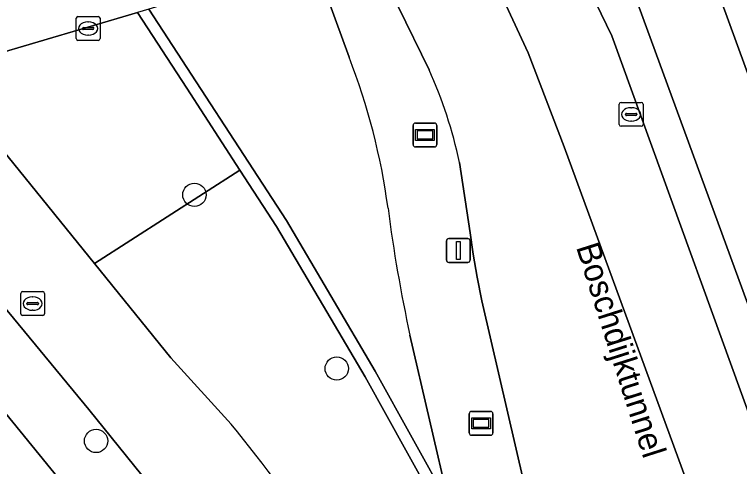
# Model space of a CAD drawing. Extents: x 160806 to 161707, y 383696 to 384148.
# Drawn here: x 161055.47 to 161085.88, y 383764.83 to 383783.78 of the extents above; entities that cross this region are included whole.
import ezdxf

# ---------------------------------------------------------------- set-up
doc = ezdxf.new("R2010")
doc.units = 0
for name, color, linetype in [('IMGEO_Berm_groen', 7, 'Continuous'), ('IMGEO_Berm_halfverhard', 7, 'Continuous'), ('IMGEO_Boom', 7, 'Continuous'), ('IMGEO_Brandkraan', 7, 'Continuous'), ('IMGEO_Fietspad_open', 7, 'Continuous'), ('IMGEO_Groenvoorziening', 7, 'Continuous'), ('IMGEO_Kolk', 7, 'Continuous'), ('IMGEO_Lichtmast', 7, 'Continuous'), ('IMGEO_Muur', 7, 'Continuous'), ('IMGEO_Openbare_ruimte_label', 7, 'Continuous'), ('IMGEO_OVBaan_gesloten', 7, 'Continuous'), ('IMGEO_Reclamebord', 7, 'Continuous'), ('IMGEO_Rijbaan_lokaal_gesloten', 7, 'Continuous'), ('IMGEO_Rioolput', 7, 'Continuous'), ('IMGEO_Voetpad_open', 7, 'Continuous'), ('IMGEO_Wegwijzer', 7, 'Continuous')]:
    doc.layers.add(name, color=color, linetype=linetype)

msp = doc.modelspace()

# ---------------------------------------------------------------- linework, layer by layer
at = {"layer": 'IMGEO_Berm_groen'}
msp.add_lwpolyline([(161069.508, 383781.989), (161068.01, 383786.104), (161061.104, 383784.003), (161066.874, 383775.139), (161070.603, 383768.827), (161073.707, 383763.229), (161072.059, 383770.328)], dxfattribs=at)
for centre, radius, start, end in [((161043.761, 383771.984), 27.622, 7.645, 21.2353), ((161134.494, 383783.86), 63.885, 187.37512, 192.22857)]:
    msp.add_arc(centre, radius, start, end, dxfattribs=at)
at = {"layer": 'IMGEO_Berm_halfverhard'}
msp.add_lwpolyline([(161086.058, 383784.64), (161083.782, 383790.902), (161082.829, 383790.612), (161096.146, 383754.129), (161097.094, 383754.459)], close=True, dxfattribs=at)
for points in [[(161080.062, 383788.476), (161079.546, 383789.613), (161078.224, 383789.211), (161077.524, 383788.998), (161078.277, 383787.537), (161080.521, 383782.879), (161094.759, 383743.637)], [(161095.134, 383747.328), (161080.062, 383788.476)]]:
    msp.add_lwpolyline(points, dxfattribs=at)
at = {"layer": 'IMGEO_Boom'}
for centre in [(161063.016, 383776.218), (161068.987, 383768.934), (161058.891, 383765.899)]:
    msp.add_circle(centre, 0.489, dxfattribs=at)
at = {"layer": 'IMGEO_Brandkraan'}
for p, q in [((161055.804, 383772.159), (161056.656, 383772.159)), ((161055.729, 383771.233), (161055.729, 383772.085)), ((161056.217, 383771.939), (161056.242, 383771.939)), ((161056.73, 383772.085), (161056.73, 383771.233)), ((161055.988, 383771.653), (161055.988, 383771.665)), ((161056.426, 383771.616), (161056.028, 383771.616)), ((161056.031, 383771.702), (161056.429, 383771.702)), ((161056.472, 383771.665), (161056.472, 383771.653)), ((161056.24, 383771.379), (161056.215, 383771.379)), ((161056.656, 383771.159), (161055.804, 383771.159))]:
    msp.add_line(p, q, dxfattribs=at)
for points in [[(161055.804, 383772.159), (161056.656, 383772.159)], [(161055.729, 383771.233), (161055.729, 383772.085)], [(161056.73, 383772.085), (161056.73, 383771.233)], [(161056.656, 383771.159), (161055.804, 383771.159)]]:
    msp.add_lwpolyline(points, dxfattribs=at)
for centre, radius, start, end in [((161055.806, 383772.083), 0.0765, 91.552, 178.448), ((161055.806, 383772.083), 0.0765, 91.552, 178.448), ((161056.654, 383772.083), 0.0765, 1.552, 88.448), ((161056.654, 383772.083), 0.0765, 1.552, 88.448), ((161056.028, 383771.662), 0.0403, 85.8775, 175.7526), ((161056.025, 383771.652), 0.0366, 178.938, 274.7102), ((161056.429, 383771.659), 0.043, 264.8664, 352.4533), ((161056.433, 383771.664), 0.0386, 1.7309, 96.639), ((161055.806, 383771.235), 0.0765, 181.552, 268.448), ((161055.806, 383771.235), 0.0765, 181.552, 268.448), ((161056.654, 383771.235), 0.0765, 271.552, 358.448), ((161056.654, 383771.235), 0.0765, 271.552, 358.448)]:
    msp.add_arc(centre, radius, start, end, dxfattribs=at)
for centre, major_axis, ratio, start_param, end_param in [((161056.216, 383771.659), (-0.387, 0.002), 0.722429, 4.712389, 7.853982), ((161056.241, 383771.659), (-0.39, 0.002), 0.717154, 1.570796, 4.712389)]:
    msp.add_ellipse(centre, major_axis=major_axis, ratio=ratio, start_param=start_param, end_param=end_param, dxfattribs=at)
at = {"layer": 'IMGEO_Fietspad_open'}
for points in [[(161064.553, 383766.608), (161062.033, 383769.384), (161058.823, 383773.343), (161052.286, 383781.408), (161048.16, 383779.877)], [(161048.827, 383779.023), (161058.581, 383767.212), (161063.615, 383760.981)]]:
    msp.add_lwpolyline(points, dxfattribs=at)
msp.add_arc((160988.276, 383704.668), 98.259, 35.17137, 39.0782, dxfattribs=at)
at = {"layer": 'IMGEO_Groenvoorziening'}
msp.add_lwpolyline([(161062.692, 383780.695), (161060.635, 383783.865), (161052.286, 383781.408), (161058.823, 383773.343), (161064.925, 383777.254)], close=True, dxfattribs=at)
for points in [[(161066.462, 383774.885), (161064.925, 383777.254), (161058.823, 383773.343), (161062.033, 383769.384), (161064.553, 383766.608)], [(161053.727, 383764.339), (161055.888, 383755.75), (161062.76, 383757.656), (161048.332, 383775.339)], [(161071.934, 383755.585), (161072.088, 383755.217), (161073.898, 383750.874), (161074.242, 383750), (161077.712, 383741.17), (161080.57, 383734.119), (161080.705, 383733.661), (161084.716, 383740.669), (161084.276, 383740.472), (161079.903, 383750), (161075.811, 383758.082), (161073.73, 383762.192), (161070.184, 383768.589), (161066.462, 383774.885)]]:
    msp.add_lwpolyline(points, dxfattribs=at)
msp.add_arc((160988.276, 383704.668), 98.259, 35.17137, 39.0782, dxfattribs=at)
at = {"layer": 'IMGEO_Kolk'}
for p, q in [((161058.056, 383782.768), (161058.056, 383783.62)), ((161058.131, 383783.694), (161058.983, 383783.694)), ((161058.544, 383783.474), (161058.569, 383783.474)), ((161059.057, 383783.62), (161059.057, 383782.768)), ((161058.315, 383783.188), (161058.315, 383783.2)), ((161058.753, 383783.151), (161058.355, 383783.151)), ((161058.358, 383783.237), (161058.756, 383783.237)), ((161058.799, 383783.2), (161058.799, 383783.188)), ((161058.567, 383782.914), (161058.542, 383782.914)), ((161058.983, 383782.694), (161058.131, 383782.694))]:
    msp.add_line(p, q, dxfattribs=at)
for points in [[(161058.056, 383782.768), (161058.056, 383783.62)], [(161058.131, 383783.694), (161058.983, 383783.694)], [(161059.057, 383783.62), (161059.057, 383782.768)], [(161058.983, 383782.694), (161058.131, 383782.694)]]:
    msp.add_lwpolyline(points, dxfattribs=at)
for centre, radius, start, end in [((161058.133, 383783.618), 0.0765, 91.552, 178.448), ((161058.133, 383783.618), 0.0765, 91.552, 178.448), ((161058.981, 383783.618), 0.0765, 1.552, 88.448), ((161058.981, 383783.618), 0.0765, 1.552, 88.448), ((161058.355, 383783.197), 0.0403, 85.8775, 175.7526), ((161058.352, 383783.187), 0.0366, 178.938, 274.7102), ((161058.756, 383783.194), 0.043, 264.8664, 352.4533), ((161058.76, 383783.199), 0.0386, 1.7309, 96.639), ((161058.133, 383782.77), 0.0765, 181.552, 268.448), ((161058.133, 383782.77), 0.0765, 181.552, 268.448), ((161058.981, 383782.77), 0.0765, 271.552, 358.448), ((161058.981, 383782.77), 0.0765, 271.552, 358.448)]:
    msp.add_arc(centre, radius, start, end, dxfattribs=at)
for centre, major_axis, ratio, start_param, end_param in [((161058.543, 383783.194), (-0.387, 0.002), 0.722429, 4.712389, 7.853982), ((161058.568, 383783.194), (-0.39, 0.002), 0.717154, 1.570796, 4.712389)]:
    msp.add_ellipse(centre, major_axis=major_axis, ratio=ratio, start_param=start_param, end_param=end_param, dxfattribs=at)
at = {"layer": 'IMGEO_Lichtmast'}
for p, q in [((161073.689, 383774.384), (161074.479, 383774.384)), ((161074.479, 383774.384), (161073.689, 383774.384)), ((161073.589, 383773.484), (161073.589, 383774.284)), ((161073.589, 383774.284), (161073.589, 383773.484)), ((161074.579, 383774.284), (161074.579, 383773.484)), ((161074.579, 383773.484), (161074.579, 383774.284)), ((161074.479, 383773.384), (161073.689, 383773.384)), ((161073.689, 383773.384), (161074.479, 383773.384))]:
    msp.add_line(p, q, dxfattribs=at)
msp.add_lwpolyline([(161074.009, 383774.259), (161074.159, 383774.259), (161074.159, 383773.509), (161074.009, 383773.509), (161074.009, 383774.259)], dxfattribs=at)
for centre, start, end in [((161073.689, 383774.284), 90, 180), ((161073.689, 383774.284), 90, 180), ((161074.479, 383774.284), 0, 90), ((161074.479, 383774.284), 360, 90), ((161073.689, 383773.484), 180, 270), ((161073.689, 383773.484), 180, 270), ((161074.479, 383773.484), 270, 0), ((161074.479, 383773.484), 270, 0)]:
    msp.add_arc(centre, 0.1, start, end, dxfattribs=at)
at = {"layer": 'IMGEO_Muur'}
msp.add_lwpolyline([(161073.707, 383763.229), (161070.603, 383768.827), (161066.874, 383775.139), (161061.104, 383784.003), (161060.635, 383783.865), (161062.692, 383780.695), (161064.925, 383777.254), (161066.462, 383774.885), (161070.184, 383768.589), (161073.73, 383762.192), (161075.811, 383758.082), (161079.903, 383750), (161084.276, 383740.472), (161084.716, 383740.669), (161080.436, 383750)], close=True, dxfattribs=at)
at = {"layer": 'IMGEO_OVBaan_gesloten'}
msp.add_lwpolyline([(161098.248, 383750), (161097.827, 383750), (161097.566, 383750.295), (161097.284, 383751.013), (161096.146, 383754.129), (161082.829, 383790.612), (161079.643, 383789.643), (161080.062, 383788.476), (161095.134, 383747.328)], dxfattribs=at)
at = {"layer": 'IMGEO_Reclamebord'}
for p, q in [((161074.546, 383766.238), (161074.546, 383767.038)), ((161074.546, 383767.038), (161074.546, 383766.238)), ((161074.646, 383767.138), (161075.436, 383767.138)), ((161075.436, 383767.138), (161074.646, 383767.138)), ((161075.536, 383767.038), (161075.536, 383766.238)), ((161075.536, 383766.238), (161075.536, 383767.038)), ((161075.436, 383766.138), (161074.646, 383766.138)), ((161074.646, 383766.138), (161075.436, 383766.138))]:
    msp.add_line(p, q, dxfattribs=at)
for points in [[(161074.647, 383766.87), (161075.435, 383766.87), (161075.435, 383766.406), (161074.647, 383766.406), (161074.647, 383766.87)], [(161074.712, 383766.805), (161074.712, 383766.471), (161075.37, 383766.471), (161075.37, 383766.805), (161074.712, 383766.805)]]:
    msp.add_lwpolyline(points, dxfattribs=at)
for centre, start, end in [((161074.646, 383767.038), 90, 180), ((161074.646, 383767.038), 90, 180), ((161075.436, 383767.038), 0, 90), ((161075.436, 383767.038), 360, 90), ((161074.646, 383766.238), 180, 270), ((161074.646, 383766.238), 180, 270), ((161075.436, 383766.238), 270, 0), ((161075.436, 383766.238), 270, 0)]:
    msp.add_arc(centre, 0.1, start, end, dxfattribs=at)
at = {"layer": 'IMGEO_Rijbaan_lokaal_gesloten'}
for points in [[(161080.521, 383782.879), (161078.277, 383787.537), (161077.524, 383788.998), (161075.001, 383788.231), (161074.06, 383787.945), (161075.725, 383784.96), (161077.022, 383782.168), (161078.529, 383778.234), (161084.322, 383762.444), (161094.418, 383735.279), (161098.056, 383725.946), (161105.565, 383706.821), (161108.924, 383707.18), (161108.812, 383707.52), (161103.024, 383722.158)], [(161074.06, 383787.945), (161071.12, 383787.05), (161070.257, 383786.787), (161072.86, 383781.463)], [(161097.209, 383718.989), (161102.075, 383706.764), (161102.196, 383706.461), (161105.565, 383706.821), (161098.056, 383725.946), (161094.418, 383735.279), (161084.322, 383762.444), (161078.529, 383778.234), (161077.022, 383782.168), (161075.725, 383784.96), (161074.06, 383787.945)], [(161094.759, 383743.637), (161080.521, 383782.879)], [(161074.138, 383777.58), (161074.579, 383774.627), (161074.704, 383773.732), (161074.871, 383772.76), (161075.07, 383771.78), (161077.219, 383762.531)]]:
    msp.add_lwpolyline(points, dxfattribs=at)
msp.add_arc((161054.965, 383773.421), 19.619, 12.2378, 24.1977, dxfattribs=at)
at = {"layer": 'IMGEO_Rioolput'}
for p, q in [((161080.912, 383780.092), (161081.764, 383780.092)), ((161080.837, 383779.166), (161080.837, 383780.018)), ((161081.325, 383779.872), (161081.35, 383779.872)), ((161081.838, 383780.018), (161081.838, 383779.166)), ((161081.096, 383779.586), (161081.096, 383779.598)), ((161081.534, 383779.549), (161081.136, 383779.549)), ((161081.139, 383779.635), (161081.537, 383779.635)), ((161081.58, 383779.598), (161081.58, 383779.586)), ((161081.348, 383779.312), (161081.323, 383779.312)), ((161081.764, 383779.092), (161080.912, 383779.092))]:
    msp.add_line(p, q, dxfattribs=at)
for points in [[(161080.912, 383780.092), (161081.764, 383780.092)], [(161080.837, 383779.166), (161080.837, 383780.018)], [(161081.838, 383780.018), (161081.838, 383779.166)], [(161081.764, 383779.092), (161080.912, 383779.092)]]:
    msp.add_lwpolyline(points, dxfattribs=at)
for centre, radius, start, end in [((161080.914, 383780.016), 0.0765, 91.552, 178.448), ((161080.914, 383780.016), 0.0765, 91.552, 178.448), ((161081.762, 383780.016), 0.0765, 1.552, 88.448), ((161081.762, 383780.016), 0.0765, 1.552, 88.448), ((161081.136, 383779.595), 0.0403, 85.8775, 175.7526), ((161081.133, 383779.585), 0.0366, 178.938, 274.7102), ((161081.537, 383779.592), 0.043, 264.8664, 352.4533), ((161081.541, 383779.597), 0.0386, 1.7309, 96.639), ((161080.914, 383779.168), 0.0765, 181.552, 268.448), ((161080.914, 383779.168), 0.0765, 181.552, 268.448), ((161081.762, 383779.168), 0.0765, 271.552, 358.448), ((161081.762, 383779.168), 0.0765, 271.552, 358.448)]:
    msp.add_arc(centre, radius, start, end, dxfattribs=at)
for centre, major_axis, ratio, start_param, end_param in [((161081.324, 383779.592), (-0.387, 0.002), 0.722429, 4.712389, 7.853982), ((161081.349, 383779.592), (-0.39, 0.002), 0.717154, 1.570796, 4.712389)]:
    msp.add_ellipse(centre, major_axis=major_axis, ratio=ratio, start_param=start_param, end_param=end_param, dxfattribs=at)
at = {"layer": 'IMGEO_Voetpad_open'}
for points in [[(161072.86, 383781.463), (161070.257, 383786.787), (161068.01, 383786.104), (161069.508, 383781.989)], [(161051.286, 383782.642), (161052.286, 383781.408), (161060.635, 383783.865)], [(161063.615, 383760.981), (161058.581, 383767.212), (161048.827, 383779.023)], [(161077.219, 383762.531), (161075.07, 383771.78), (161074.871, 383772.76), (161074.704, 383773.732), (161074.579, 383774.627), (161074.138, 383777.58)], [(161047.132, 383776.763), (161048.332, 383775.339), (161062.76, 383757.656), (161055.888, 383755.75), (161056.095, 383754.925), (161057.032, 383755.173), (161059.57, 383755.846), (161063.041, 383756.765), (161063.185, 383756.803), (161064.704, 383757.206), (161064.776, 383756.791), (161066.348, 383757.197)], [(161072.059, 383770.328), (161073.707, 383763.229), (161080.436, 383750), (161084.716, 383740.669), (161080.705, 383733.661), (161081.06, 383732.456), (161081.638, 383732.72), (161082.05, 383732.909)]]:
    msp.add_lwpolyline(points, dxfattribs=at)
for centre, radius, start, end in [((161043.761, 383771.984), 27.622, 7.645, 21.2353), ((161054.965, 383773.421), 19.619, 12.2378, 24.1977), ((161134.494, 383783.86), 63.885, 187.37512, 192.22857)]:
    msp.add_arc(centre, radius, start, end, dxfattribs=at)
at = {"layer": 'IMGEO_Wegwijzer'}
for p, q in [((161072.291, 383779.229), (161073.081, 383779.229)), ((161073.081, 383779.229), (161072.291, 383779.229)), ((161072.191, 383778.329), (161072.191, 383779.129)), ((161072.191, 383779.129), (161072.191, 383778.329)), ((161073.181, 383779.129), (161073.181, 383778.329)), ((161073.181, 383778.329), (161073.181, 383779.129)), ((161073.081, 383778.229), (161072.291, 383778.229)), ((161072.291, 383778.229), (161073.081, 383778.229))]:
    msp.add_line(p, q, dxfattribs=at)
for points in [[(161072.292, 383778.961), (161073.08, 383778.961), (161073.08, 383778.497), (161072.292, 383778.497), (161072.292, 383778.961)], [(161072.357, 383778.896), (161072.357, 383778.562), (161073.015, 383778.562), (161073.015, 383778.896), (161072.357, 383778.896)]]:
    msp.add_lwpolyline(points, dxfattribs=at)
for centre, start, end in [((161072.291, 383779.129), 90, 180), ((161072.291, 383779.129), 90, 180), ((161073.081, 383779.129), 0, 90), ((161073.081, 383779.129), 360, 90), ((161072.291, 383778.329), 180, 270), ((161072.291, 383778.329), 180, 270), ((161073.081, 383778.329), 270, 0), ((161073.081, 383778.329), 270, 0)]:
    msp.add_arc(centre, 0.1, start, end, dxfattribs=at)

# ---------------------------------------------------------------- texts
at = {"layer": 'IMGEO_Openbare_ruimte_label'}
msp.add_text('Boschdijktunnel', height=1, rotation=287.6923, dxfattribs=at).set_placement((161079.018, 383774.033))

doc.saveas('drawing.dxf')
